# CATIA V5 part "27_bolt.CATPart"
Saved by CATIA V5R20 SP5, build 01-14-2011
Part number: 27_bolt
Bounding box of the stored display mesh (mm): x -15 to 15, y 23.862 to 56.042, z -15 to 15
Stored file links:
  C:\Documents and Settings\anizard\Bureau\13\27_bolt.CATPart
  C:\Documents and Settings\anizard\Bureau\13\anizard.CATProduct
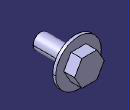
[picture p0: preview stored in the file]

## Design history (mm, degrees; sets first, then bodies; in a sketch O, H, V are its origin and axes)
Set1
  Point1: linked copy from another document
  Plane1: linked copy from another document
Body1 (main body)
  Sketch1 on Plane1, origin (0, 46.8619, 0), H (-1, 0, 0), V (0, 0, 1)
    circle A1 centre (0, 0) radius 15
    point P1 (0, 0)
    reference projected point E1 (0, 0) from Point1
    radius A1 = 15
    coincidence: E1 P1
  Pad1: profile Sketch1, direction (0, 1, 0), length 2
  Sketch2 on start face of Pad1, origin (0, 46.8619, 0), H (-1, 0, 0), V (0, 0, 1)
    circle A1 centre (0, 0) radius 5
    point P2 (5, 0)
    reference projected circle E1 centre (0, 0) radius 15 from edge [face of Pad1 from Sketch1.A1 | end face of Pad1]
    radius A1 = 5
    coincidence: A1 P2, P2 H
    concentricity: A1 E1
  Pad2: profile Sketch2, direction (0, -1, 0), length 23
  Sketch3 on end face of Pad1, origin (0, 48.8619, 0), H (-1, 0, 0), V (0, 0, 1)
    point P1 (0, 0)
    point P2 (4.9, -8.487)
    point P3 (9.8, 0)
    point P4 (4.9, 8.487)
    point P5 (-4.9, 8.487)
    point P6 (-9.8, 0)
    point P7 (-4.9, -8.487)
    point P8 (7.35, -4.2435)
    line L1 (4.9, -8.487) -> (9.8, 0)
    line L2 (9.8, 0) -> (4.9, 8.487)
    line L3 (4.9, 8.487) -> (-4.9, 8.487)
    line L4 (-4.9, 8.487) -> (-9.8, 0)
    line L5 (-9.8, 0) -> (-4.9, -8.487)
    line L6 (-4.9, -8.487) -> (4.9, -8.487)
    construction line L7 (0, 0) -> (7.35, -4.2435)
    construction circle A1 centre (0, 0) radius 9.8
    construction arc A2 centre (-9.8, 0) radius 9.8 from (-4.9, 8.487) to (-4.9, -8.487) cw
    construction arc A3 centre (9.8, 0) radius 9.8 from (4.9, 8.487) to (4.9, -8.487) ccw
    reference projected circle E1 centre (0, 0) radius 15 from edge [face of Pad1 from Sketch1.A1 | end face of Pad1]
    radius A1 = 9.8
    coincidence: A1 P2, A1 P3, A1 P4, A1 P5, A1 P6, A1 P7, A2 P1, A3 P1
    midpoint: P8 L1
    parallelism: L1 L4
    concentricity: A1 E1
    horizontal: L3 H
  Pad3: profile Sketch3, direction (0, 1, 0), length 7.18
